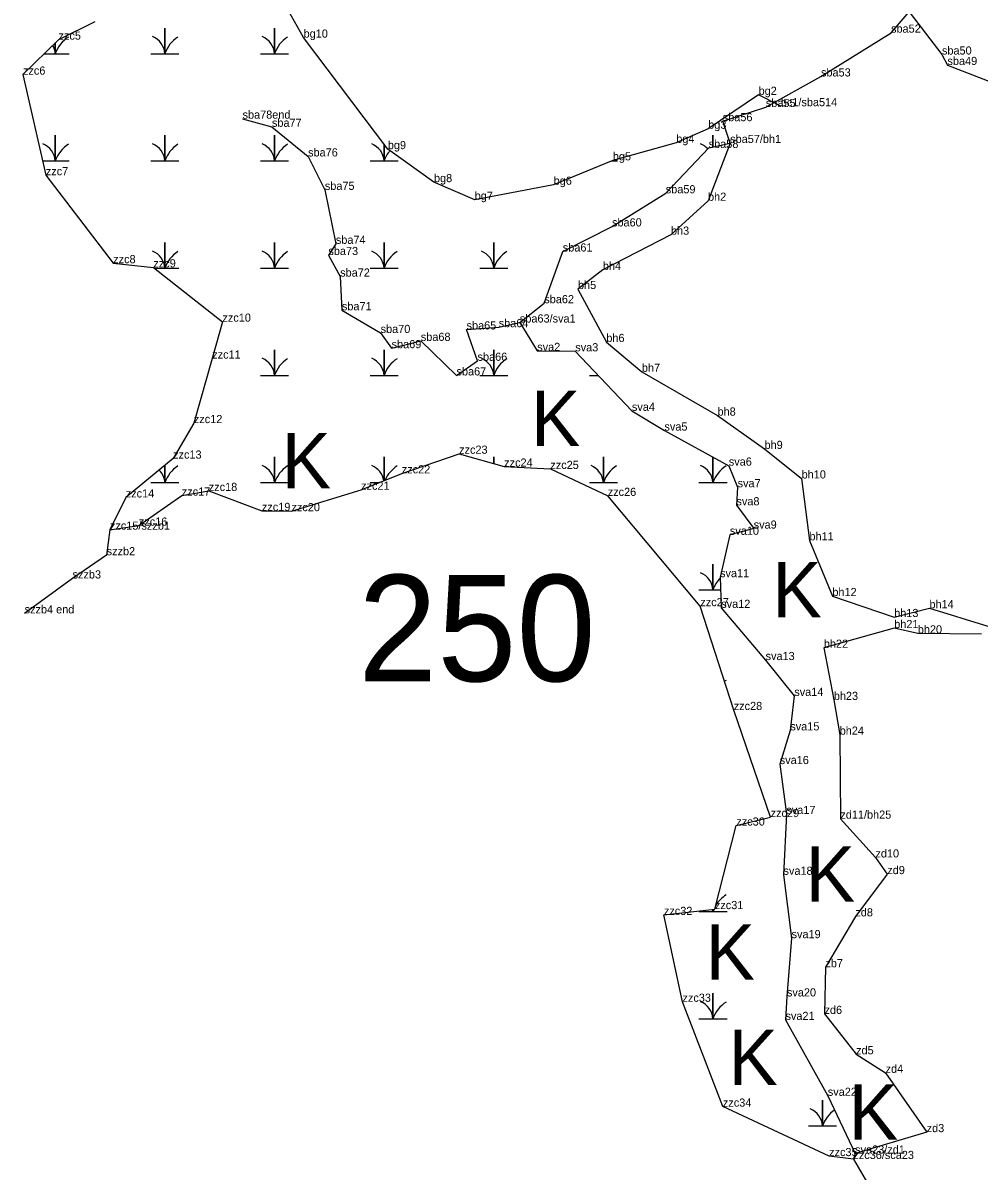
# Model space of a CAD drawing. Extents: x 2072529 to 2268796, y 436423 to 470406.
# Drawn here: x 2211555 to 2212142, y 440022 to 440726 of the extents above; entities that cross this region are included whole.
import ezdxf

# ---------------------------------------------------------------- set-up
doc = ezdxf.new("R2010")
doc.units = 0
for name, color, linetype in [('Default', 7, 'Continuous'), ('Exist Environmental Wetland Boundary', 7, 'Continuous'), ('Exist Environmental Wetland Boundary Cogo Comment', 7, 'Continuous'), ('Exist Hydro Jurisdictional Stream or Body of Water NEU Mitigable', 7, 'Continuous'), ('Exist Hydro Jurisdictional Stream or Body of Water NEU Mitigable Cogo Comment', 7, 'Continuous'), ('Exist Hydro Swamp or Marsh', 7, 'Continuous'), ('Old_Level_20', 7, 'Continuous')]:
    doc.layers.add(name, color=color, linetype=linetype)

msp = doc.modelspace()

# ---------------------------------------------------------------- linework, layer by layer
at = {"layer": 'Exist Environmental Wetland Boundary'}
for points in [[(2212020.07, 440675.03), (2212006.43, 440682), (2211975.5, 440661.2), (2211955.93, 440652.57), (2211917, 440641.78), (2211880.68, 440626.83), (2211832.24, 440617.61), (2211807.27, 440628.42), (2211778.97, 440648.69), (2211727.28, 440717.11), (2211717.96, 440733.5)], [(2211599.12, 440726.88), (2211576.92, 440715.86), (2211555.11, 440694.4), (2211569.12, 440632.64), (2211610.45, 440578.68), (2211635.11, 440576.11), (2211677.48, 440542.8), (2211671.21, 440520.15), (2211659.96, 440480.57), (2211647.22, 440458.77), (2211618.17, 440434.92), (2211608.46, 440415.15), (2211626.21, 440417.64), (2211652.55, 440436.05), (2211669.1, 440438.91), (2211701.69, 440426.65), (2211719.83, 440426.51), (2211762.55, 440439.65), (2211787.51, 440449.71), (2211822.68, 440461.76), (2211850.33, 440453.85), (2211878.65, 440452.42), (2211913.86, 440435.88)], [(2211988.98, 440652.44), (2211975.4, 440617), (2211952.66, 440596.19), (2211910.87, 440574.52), (2211895.62, 440562.82), (2211913.01, 440530.33), (2211934.81, 440512.04), (2211981.23, 440485.15), (2212010.06, 440464.72), (2212032.82, 440446.59), (2212037.61, 440408.61), (2212051.68, 440374.42), (2212089.59, 440361.54), (2212111.25, 440366.96), (2212147.05, 440355.87)], [(2212064.56, 440028.96), (2212049.69, 440030.74), (2211984.51, 440061.11), (2211959.71, 440125.46), (2211948.32, 440178.74), (2211979.6, 440182.31), (2211992.76, 440233.59), (2212013.8, 440238.8), (2211991.16, 440304.5), (2211970.67, 440368.22), (2211913.86, 440435.88)], [(2212143.11, 440351.05), (2212104.1, 440351.49), (2212089.64, 440354.75), (2212046.45, 440342.68), (2212052.57, 440310.67), (2212056.18, 440289.36), (2212056.58, 440237.81), (2212078.1, 440214), (2212085.36, 440203.8), (2212065.77, 440177.84), (2212047.38, 440146.64), (2212046.85, 440117.99), (2212066.23, 440093.22), (2212084.33, 440081.87), (2212109.54, 440045.45), (2212065.67, 440032.29)]]:
    msp.add_lwpolyline(points, dxfattribs=at)
at = {"layer": 'Exist Hydro Jurisdictional Stream or Body of Water NEU Mitigable'}
for points in [[(2211689.83, 440667.36), (2211707.85, 440662.39), (2211730.03, 440644.2), (2211740.31, 440623.69), (2211747.06, 440590.59), (2211742.49, 440583.7), (2211749.71, 440570.47), (2211750.77, 440549.79), (2211774.54, 440535.87), (2211781.27, 440526.52), (2211799.19, 440531.02), (2211821.09, 440509.82), (2211834, 440518.8), (2211827.26, 440538.02), (2211846.98, 440539.42), (2211859.97, 440542.28), (2211874.94, 440554.14), (2211886.3, 440585.87), (2211916.49, 440601.25), (2211949.48, 440621.58), (2211975.8, 440649.4), (2211988.98, 440652.44), (2211984.44, 440665.82), (2212010.84, 440674.52), (2212044.7, 440693.29), (2212087.68, 440720.16), (2212098.89, 440732.89), (2212118.92, 440706.73), (2212122.3, 440700.31), (2212150.31, 440689.4)], [(2211859.97, 440542.28), (2211870.61, 440524.83), (2211893.94, 440524.61), (2211928.71, 440488.08), (2211948.65, 440475.96), (2211988.14, 440454.44), (2211993.55, 440441.2), (2211992.83, 440430.12), (2212003.41, 440415.8), (2211988.8, 440412.02), (2211982.78, 440386.01), (2211983.49, 440367.18), (2212010.7, 440335.15), (2212028.31, 440313.12), (2212025.88, 440291.99), (2212019.4, 440271.32), (2212023.47, 440240.67), (2212021.7, 440203.38), (2212026.64, 440164.49), (2212023.8, 440128.72), (2212022.92, 440114.3), (2212048.88, 440067.75), (2212065.67, 440032.29), (2212064.56, 440028.96), (2212076.06, 440009.22)], [(2211608.46, 440415.15), (2211606.45, 440399.48), (2211585.53, 440385.21), (2211556.12, 440363.79)]]:
    msp.add_lwpolyline(points, dxfattribs=at)
at = {"layer": 'Exist Hydro Swamp or Marsh'}
for points in [[(2211633.58, 440707.24), (2211642.19, 440707.24), (2211642.19, 440723.02), (2211642.19, 440707.24), (2211650.79, 440707.24)], [(2211700.83, 440707.24), (2211709.44, 440707.24), (2211709.44, 440723.02), (2211709.44, 440707.24), (2211718.04, 440707.24)], [(2211568.15, 440707.24), (2211574.94, 440707.24), (2211574.94, 440713.91)], [(2211574.94, 440713.91), (2211574.94, 440707.24), (2211583.54, 440707.24)], [(2211567.12, 440641.44), (2211574.94, 440641.44), (2211574.94, 440657.22), (2211574.94, 440641.44), (2211583.54, 440641.44)], [(2211633.58, 440641.44), (2211642.19, 440641.44), (2211642.19, 440657.22), (2211642.19, 440641.44), (2211650.79, 440641.44)], [(2211700.83, 440641.44), (2211709.44, 440641.44), (2211709.44, 440657.22), (2211709.44, 440641.44), (2211718.04, 440641.44)], [(2211978.44, 440650.01), (2211978.44, 440657.22), (2211978.44, 440650.01)], [(2211768.08, 440641.44), (2211776.69, 440641.44), (2211776.69, 440651.72)], [(2211776.69, 440651.72), (2211776.69, 440641.44), (2211785.29, 440641.44)], [(2211916.17, 440641.44), (2211919.79, 440641.44)], [(2211635.71, 440575.64), (2211642.19, 440575.64), (2211642.19, 440591.42), (2211642.19, 440575.64), (2211650.79, 440575.64)], [(2211700.83, 440575.64), (2211709.44, 440575.64), (2211709.44, 440591.42), (2211709.44, 440575.64), (2211718.04, 440575.64)], [(2211768.08, 440575.64), (2211776.69, 440575.64), (2211776.69, 440591.42), (2211776.69, 440575.64), (2211785.29, 440575.64)], [(2211835.33, 440575.64), (2211843.94, 440575.64), (2211843.94, 440591.42), (2211843.94, 440575.64), (2211852.54, 440575.64)], [(2211700.83, 440509.84), (2211709.44, 440509.84), (2211709.44, 440525.62), (2211709.44, 440509.84), (2211718.04, 440509.84)], [(2211768.08, 440509.84), (2211776.69, 440509.84), (2211776.69, 440525.62), (2211776.69, 440509.84), (2211785.29, 440509.84)], [(2211835.33, 440509.84), (2211843.94, 440509.84), (2211843.94, 440525.62), (2211843.94, 440509.84), (2211852.54, 440509.84)], [(2211902.58, 440509.84), (2211908, 440509.84)], [(2211700.83, 440444.04), (2211709.44, 440444.04), (2211709.44, 440459.82), (2211709.44, 440444.04), (2211718.04, 440444.04)], [(2211776.69, 440445.34), (2211776.69, 440459.82), (2211776.69, 440445.34)], [(2211843.94, 440455.68), (2211843.94, 440459.82), (2211843.94, 440455.68)], [(2211902.58, 440444.04), (2211911.19, 440444.04), (2211911.19, 440459.82), (2211911.19, 440444.04), (2211919.79, 440444.04)], [(2211969.83, 440444.04), (2211978.44, 440444.04), (2211978.44, 440459.73)], [(2211978.44, 440459.73), (2211978.44, 440444.04), (2211987.04, 440444.04)], [(2211633.58, 440444.04), (2211642.19, 440444.04), (2211642.19, 440454.63)], [(2211642.19, 440454.63), (2211642.19, 440444.04), (2211650.79, 440444.04)], [(2211768.08, 440444.04), (2211773.44, 440444.04)], [(2211969.83, 440378.24), (2211978.44, 440378.24), (2211978.44, 440394.02), (2211978.44, 440378.24), (2211983.07, 440378.24)], [(2211969.83, 440180.84), (2211978.44, 440180.84), (2211978.44, 440182.18)], [(2211978.44, 440182.18), (2211978.44, 440180.84), (2211987.04, 440180.84)], [(2211969.83, 440115.04), (2211978.44, 440115.04), (2211978.44, 440130.82), (2211978.44, 440115.04), (2211987.04, 440115.04)], [(2212037.08, 440049.24), (2212045.69, 440049.24), (2212045.69, 440065.02), (2212045.69, 440049.24), (2212054.29, 440049.24)]]:
    msp.add_lwpolyline(points, dxfattribs=at)
for centre, radius, start, end in [((2211593.18, 440701.18), 19.22, 122.12745, 161.62219), ((2211629.92, 440706.35), 12.3, 4.14034, 67.53497), ((2211660.43, 440701.18), 19.22, 122.12745, 161.62219), ((2211697.17, 440706.35), 12.3, 4.14034, 67.53497), ((2211727.68, 440701.18), 19.22, 122.12745, 161.62219), ((2211562.67, 440706.35), 12.3, 4.14034, 29.39022), ((2211562.67, 440640.55), 12.3, 4.14034, 67.53497), ((2211593.18, 440635.38), 19.22, 122.12745, 161.62219), ((2211629.92, 440640.55), 12.3, 4.14034, 67.53497), ((2211660.43, 440635.38), 19.22, 122.12745, 161.62219), ((2211697.17, 440640.55), 12.3, 4.14034, 67.53497), ((2211727.68, 440635.38), 19.22, 122.12745, 161.62219), ((2211764.42, 440640.55), 12.3, 4.14034, 67.53497), ((2211794.93, 440635.38), 19.22, 139.80689, 161.62219), ((2211966.17, 440640.55), 12.3, 42.34122, 67.53497), ((2211629.92, 440574.75), 12.3, 4.14034, 67.53497), ((2211660.43, 440569.58), 19.22, 122.12745, 161.62219), ((2211697.17, 440574.75), 12.3, 4.14034, 67.53497), ((2211727.68, 440569.58), 19.22, 122.12745, 161.62219), ((2211764.42, 440574.75), 12.3, 4.14034, 67.53497), ((2211794.93, 440569.58), 19.22, 122.12745, 161.62219), ((2211831.67, 440574.75), 12.3, 4.14034, 67.53497), ((2211862.18, 440569.58), 19.22, 122.12745, 161.62219), ((2211697.17, 440508.95), 12.3, 4.14034, 67.53497), ((2211727.68, 440503.78), 19.22, 122.12745, 161.62219), ((2211764.42, 440508.95), 12.3, 4.14034, 67.53497), ((2211794.93, 440503.78), 19.22, 122.12745, 161.62219), ((2211831.67, 440508.95), 12.3, 4.14034, 67.53497), ((2211862.18, 440503.78), 19.22, 122.12745, 161.62219), ((2211629.92, 440443.15), 12.3, 4.14034, 44.48978), ((2211660.43, 440437.98), 19.22, 122.12745, 161.62219), ((2211697.17, 440443.15), 12.3, 4.14034, 67.53497), ((2211727.68, 440437.98), 19.22, 122.12745, 161.62219), ((2211764.42, 440443.15), 12.3, 9.98945, 67.53497), ((2211794.93, 440437.98), 19.22, 122.12745, 156.69385), ((2211862.18, 440437.98), 19.22, 122.12745, 124.5773), ((2211898.92, 440443.15), 12.3, 4.14034, 67.53497), ((2211929.43, 440437.98), 19.22, 122.12745, 161.62219), ((2211966.17, 440443.15), 12.3, 4.14034, 67.53497), ((2211996.68, 440437.98), 19.22, 122.12745, 161.62219), ((2211966.17, 440377.35), 12.3, 4.14034, 67.53497), ((2211996.68, 440372.18), 19.22, 136.23499, 161.62219), ((2211996.68, 440306.38), 19.22, 122.12745, 125.46334), ((2211996.68, 440174.78), 19.22, 122.12745, 148.92072), ((2211966.17, 440179.95), 12.3, 4.14034, 10.36494), ((2211996.68, 440174.78), 19.22, 157.14906, 161.62219), ((2211966.17, 440114.15), 12.3, 4.14034, 67.53497), ((2211996.68, 440108.98), 19.22, 122.12745, 161.62219), ((2212033.42, 440048.35), 12.3, 4.14034, 67.53497), ((2212063.93, 440043.18), 19.22, 124.57887, 161.62219)]:
    msp.add_arc(centre, radius, start, end, dxfattribs=at)
at = {"layer": 'Old_Level_20'}
for p, q in [((2211576.92, 440715.86), (2211576.92, 440715.86)), ((2211727.28, 440717.11), (2211727.28, 440717.11)), ((2212087.68, 440720.16), (2212087.68, 440720.16)), ((2212118.92, 440706.73), (2212118.92, 440706.73)), ((2212122.3, 440700.31), (2212122.3, 440700.31)), ((2211555.11, 440694.4), (2211555.11, 440694.4)), ((2212044.7, 440693.29), (2212044.7, 440693.29)), ((2212006.43, 440682), (2212006.43, 440682)), ((2212010.84, 440674.52), (2212010.84, 440674.52)), ((2212020.07, 440675.03), (2212020.07, 440675.03)), ((2211689.83, 440667.36), (2211689.83, 440667.36)), ((2211707.85, 440662.39), (2211707.85, 440662.39)), ((2211975.5, 440661.2), (2211975.5, 440661.2)), ((2211984.44, 440665.82), (2211984.44, 440665.82)), ((2211955.93, 440652.57), (2211955.93, 440652.57)), ((2211988.98, 440652.44), (2211988.98, 440652.44)), ((2211988.98, 440652.44), (2211988.98, 440652.44)), ((2211778.97, 440648.69), (2211778.97, 440648.69)), ((2211975.8, 440649.4), (2211975.8, 440649.4)), ((2211730.03, 440644.2), (2211730.03, 440644.2)), ((2211917, 440641.78), (2211917, 440641.78)), ((2211569.12, 440632.64), (2211569.12, 440632.64)), ((2211807.27, 440628.42), (2211807.27, 440628.42)), ((2211880.68, 440626.83), (2211880.68, 440626.83)), ((2211740.31, 440623.69), (2211740.31, 440623.69)), ((2211832.24, 440617.61), (2211832.24, 440617.61)), ((2211949.48, 440621.58), (2211949.48, 440621.58)), ((2211975.4, 440617), (2211975.4, 440617)), ((2211916.49, 440601.25), (2211916.49, 440601.25)), ((2211952.66, 440596.19), (2211952.66, 440596.19)), ((2211747.06, 440590.59), (2211747.06, 440590.59)), ((2211742.49, 440583.7), (2211742.49, 440583.7)), ((2211886.3, 440585.87), (2211886.3, 440585.87)), ((2211610.45, 440578.68), (2211610.45, 440578.68)), ((2211635.11, 440576.11), (2211635.11, 440576.11)), ((2211749.71, 440570.47), (2211749.71, 440570.47)), ((2211910.87, 440574.52), (2211910.87, 440574.52)), ((2211895.62, 440562.82), (2211895.62, 440562.82)), ((2211874.94, 440554.14), (2211874.94, 440554.14)), ((2211750.77, 440549.79), (2211750.77, 440549.79)), ((2211677.48, 440542.8), (2211677.48, 440542.8)), ((2211859.97, 440542.28), (2211859.97, 440542.28)), ((2211774.54, 440535.87), (2211774.54, 440535.87)), ((2211827.26, 440538.02), (2211827.26, 440538.02)), ((2211846.98, 440539.42), (2211846.98, 440539.42)), ((2211781.27, 440526.52), (2211781.27, 440526.52)), ((2211799.19, 440531.02), (2211799.19, 440531.02)), ((2211913.01, 440530.33), (2211913.01, 440530.33)), ((2211671.21, 440520.15), (2211671.21, 440520.15)), ((2211834, 440518.8), (2211834, 440518.8)), ((2211870.61, 440524.83), (2211870.61, 440524.83)), ((2211893.94, 440524.61), (2211893.94, 440524.61)), ((2211934.81, 440512.04), (2211934.81, 440512.04)), ((2211821.09, 440509.82), (2211821.09, 440509.82)), ((2211928.71, 440488.08), (2211928.71, 440488.08)), ((2211981.23, 440485.15), (2211981.23, 440485.15)), ((2211659.96, 440480.57), (2211659.96, 440480.57)), ((2211948.65, 440475.96), (2211948.65, 440475.96)), ((2212010.06, 440464.72), (2212010.06, 440464.72)), ((2211647.22, 440458.77), (2211647.22, 440458.77)), ((2211822.68, 440461.76), (2211822.68, 440461.76)), ((2211787.51, 440449.71), (2211787.51, 440449.71)), ((2211850.33, 440453.85), (2211850.33, 440453.85)), ((2211878.65, 440452.42), (2211878.65, 440452.42)), ((2211988.14, 440454.44), (2211988.14, 440454.44)), ((2211993.55, 440441.2), (2211993.55, 440441.2)), ((2212032.82, 440446.59), (2212032.82, 440446.59)), ((2211618.17, 440434.92), (2211618.17, 440434.92)), ((2211652.55, 440436.05), (2211652.55, 440436.05)), ((2211669.1, 440438.91), (2211669.1, 440438.91)), ((2211762.55, 440439.65), (2211762.55, 440439.65)), ((2211913.86, 440435.88), (2211913.86, 440435.88)), ((2211992.83, 440430.12), (2211992.83, 440430.12)), ((2211701.69, 440426.65), (2211701.69, 440426.65)), ((2211719.83, 440426.51), (2211719.83, 440426.51)), ((2211608.46, 440415.15), (2211608.46, 440415.15)), ((2211608.46, 440415.15), (2211608.46, 440415.15)), ((2211626.21, 440417.64), (2211626.21, 440417.64)), ((2212003.41, 440415.8), (2212003.41, 440415.8)), ((2211988.8, 440412.02), (2211988.8, 440412.02)), ((2212037.61, 440408.61), (2212037.61, 440408.61)), ((2211606.45, 440399.48), (2211606.45, 440399.48)), ((2211606.45, 440399.48), (2211606.45, 440399.48)), ((2211585.53, 440385.21), (2211585.53, 440385.21)), ((2211585.53, 440385.21), (2211585.53, 440385.21)), ((2211982.78, 440386.01), (2211982.78, 440386.01)), ((2212051.68, 440374.42), (2212051.68, 440374.42)), ((2211556.12, 440363.79), (2211556.12, 440363.79)), ((2211556.12, 440363.79), (2211556.12, 440363.79)), ((2211970.67, 440368.22), (2211970.67, 440368.22)), ((2211983.49, 440367.18), (2211983.49, 440367.18)), ((2212111.25, 440366.96), (2212111.25, 440366.96)), ((2212089.59, 440361.54), (2212089.59, 440361.54)), ((2212089.64, 440354.75), (2212089.64, 440354.75)), ((2212104.1, 440351.49), (2212104.1, 440351.49)), ((2212046.45, 440342.68), (2212046.45, 440342.68)), ((2212010.7, 440335.15), (2212010.7, 440335.15)), ((2212028.31, 440313.12), (2212028.31, 440313.12)), ((2212052.57, 440310.67), (2212052.57, 440310.67)), ((2211991.16, 440304.5), (2211991.16, 440304.5)), ((2212025.88, 440291.99), (2212025.88, 440291.99)), ((2212056.18, 440289.36), (2212056.18, 440289.36)), ((2212019.4, 440271.32), (2212019.4, 440271.32)), ((2212013.8, 440238.8), (2212013.8, 440238.8)), ((2212023.47, 440240.67), (2212023.47, 440240.67)), ((2212056.58, 440237.81), (2212056.58, 440237.81)), ((2211992.76, 440233.59), (2211992.76, 440233.59)), ((2212078.1, 440214), (2212078.1, 440214)), ((2212021.7, 440203.38), (2212021.7, 440203.38)), ((2212085.36, 440203.8), (2212085.36, 440203.8)), ((2211979.6, 440182.31), (2211979.6, 440182.31)), ((2211948.32, 440178.74), (2211948.32, 440178.74)), ((2212065.77, 440177.84), (2212065.77, 440177.84)), ((2212026.64, 440164.49), (2212026.64, 440164.49)), ((2212047.38, 440146.64), (2212047.38, 440146.64)), ((2211959.71, 440125.46), (2211959.71, 440125.46)), ((2212023.8, 440128.72), (2212023.8, 440128.72)), ((2212046.85, 440117.99), (2212046.85, 440117.99)), ((2212022.92, 440114.3), (2212022.92, 440114.3)), ((2212066.23, 440093.22), (2212066.23, 440093.22)), ((2212084.33, 440081.87), (2212084.33, 440081.87)), ((2212048.88, 440067.75), (2212048.88, 440067.75)), ((2211984.51, 440061.11), (2211984.51, 440061.11)), ((2212109.54, 440045.45), (2212109.54, 440045.45)), ((2212049.69, 440030.74), (2212049.69, 440030.74)), ((2212064.56, 440028.96), (2212064.56, 440028.96)), ((2212064.56, 440028.96), (2212064.56, 440028.96)), ((2212065.67, 440032.29), (2212065.67, 440032.29)), ((2212065.67, 440032.29), (2212065.67, 440032.29))]:
    msp.add_line(p, q, dxfattribs=at)

# ---------------------------------------------------------------- texts
at = {"layer": 'Default'}
msp.add_text('250', height=65.34, dxfattribs=at).set_placement((2211760.71, 440322.11))
at = {"layer": 'Exist Environmental Wetland Boundary Cogo Comment'}
for s, p in [('zzc5', (2211576.92, 440715.86)), ('bg10', (2211727.28, 440717.11)), ('zzc6', (2211555.11, 440694.4)), ('bg2', (2212006.43, 440682)), ('bc1/sba514', (2212020.07, 440675.03)), ('bg3', (2211975.5, 440661.2)), ('bg9', (2211778.97, 440648.69)), ('bg4', (2211955.93, 440652.57)), ('sba57/bh1', (2211988.98, 440652.44)), ('bg5', (2211917, 440641.78)), ('zzc7', (2211569.12, 440632.64)), ('bg8', (2211807.27, 440628.42)), ('bg6', (2211880.68, 440626.83)), ('bg7', (2211832.24, 440617.61)), ('bh2', (2211975.4, 440617)), ('bh3', (2211952.66, 440596.19)), ('zzc8', (2211610.45, 440578.68)), ('zzc9', (2211635.11, 440576.11)), ('bh4', (2211910.87, 440574.52)), ('bh5', (2211895.62, 440562.82)), ('zzc10', (2211677.48, 440542.8)), ('bh6', (2211913.01, 440530.33)), ('zzc11', (2211671.21, 440520.15)), ('bh7', (2211934.81, 440512.04)), ('bh8', (2211981.23, 440485.15)), ('zzc12', (2211659.96, 440480.57)), ('bh9', (2212010.06, 440464.72)), ('zzc13', (2211647.22, 440458.77)), ('zzc23', (2211822.68, 440461.76)), ('zzc24', (2211850.33, 440453.85)), ('zzc25', (2211878.65, 440452.42)), ('zzc22', (2211787.51, 440449.71)), ('bh10', (2212032.82, 440446.59)), ('zzc17', (2211652.55, 440436.05)), ('zzc18', (2211669.1, 440438.91)), ('zzc21', (2211762.55, 440439.65)), ('zzc14', (2211618.17, 440434.92)), ('zzc26', (2211913.86, 440435.88)), ('zzc19', (2211701.69, 440426.65)), ('zzc20', (2211719.83, 440426.51)), ('zzc16', (2211626.21, 440417.64)), ('bh11', (2212037.61, 440408.61)), ('bh12', (2212051.68, 440374.42)), ('zzc27', (2211970.67, 440368.22)), ('bh14', (2212111.25, 440366.96)), ('bh13', (2212089.59, 440361.54)), ('bh21', (2212089.64, 440354.75)), ('bh20', (2212104.1, 440351.49)), ('bh22', (2212046.45, 440342.68)), ('bh23', (2212052.57, 440310.67)), ('zzc28', (2211991.16, 440304.5)), ('bh24', (2212056.18, 440289.36)), ('zzc30', (2211992.76, 440233.59)), ('zd11/bh25', (2212056.58, 440237.81)), ('zd10', (2212078.1, 440214)), ('zd9', (2212085.36, 440203.8)), ('zzc32', (2211948.32, 440178.74)), ('zzc31', (2211979.6, 440182.31)), ('zd8', (2212065.77, 440177.84)), ('zb7', (2212047.38, 440146.64)), ('zzc33', (2211959.71, 440125.46)), ('zd6', (2212046.85, 440117.99)), ('zd5', (2212066.23, 440093.22)), ('zd4', (2212084.33, 440081.87)), ('zzc34', (2211984.51, 440061.11)), ('zd3', (2212109.54, 440045.45)), ('zzc35', (2212049.69, 440030.74)), ('sva23/zd1', (2212065.67, 440032.29))]:
    msp.add_text(s, height=5, dxfattribs=at).set_placement(p)
at = {"layer": 'Exist Hydro Jurisdictional Stream or Body of Water NEU Mitigable Cogo Comment'}
for s, p in [('sba52', (2212087.68, 440720.16)), ('sba50', (2212118.92, 440706.73)), ('sba49', (2212122.3, 440700.31)), ('sba53', (2212044.7, 440693.29)), ('sba55', (2212010.84, 440674.52)), ('sba78end', (2211689.83, 440667.36)), ('sba77', (2211707.85, 440662.39)), ('sba56', (2211984.44, 440665.82)), ('sba58', (2211975.8, 440649.4)), ('sba76', (2211730.03, 440644.2)), ('sba75', (2211740.31, 440623.69)), ('sba59', (2211949.48, 440621.58)), ('sba60', (2211916.49, 440601.25)), ('sba74', (2211747.06, 440590.59)), ('sba61', (2211886.3, 440585.87)), ('sba73', (2211742.49, 440583.7)), ('sba72', (2211749.71, 440570.47)), ('sba71', (2211750.77, 440549.79)), ('sba62', (2211874.94, 440554.14)), ('sba63/sva1', (2211859.97, 440542.28)), ('sba70', (2211774.54, 440535.87)), ('sba65', (2211827.26, 440538.02)), ('sba64', (2211846.98, 440539.42)), ('sba68', (2211799.19, 440531.02)), ('sba69', (2211781.27, 440526.52)), ('sva2', (2211870.61, 440524.83)), ('sva3', (2211893.94, 440524.61)), ('sba66', (2211834, 440518.8)), ('sba67', (2211821.09, 440509.82)), ('sva4', (2211928.71, 440488.08)), ('sva5', (2211948.65, 440475.96)), ('sva6', (2211988.14, 440454.44)), ('sva7', (2211993.55, 440441.2)), ('sva8', (2211992.83, 440430.12)), ('zzc15/szzb', (2211608.46, 440415.15)), ('zzc15/szzb1', (2211608.46, 440415.15)), ('sva9', (2212003.41, 440415.8)), ('sva10', (2211988.8, 440412.02)), ('szzb2', (2211606.45, 440399.48)), ('szzb3', (2211585.53, 440385.21)), ('sva11', (2211982.78, 440386.01)), ('sva12', (2211983.49, 440367.18)), ('szzb4 end', (2211556.12, 440363.79)), ('sva13', (2212010.7, 440335.15)), ('sva14', (2212028.31, 440313.12)), ('sva15', (2212025.88, 440291.99)), ('sva16', (2212019.4, 440271.32)), ('zzc29', (2212013.8, 440238.8)), ('sva17', (2212023.47, 440240.67)), ('sva18', (2212021.7, 440203.38)), ('sva19', (2212026.64, 440164.49)), ('sva20', (2212023.8, 440128.72)), ('sva21', (2212022.92, 440114.3)), ('sva22', (2212048.88, 440067.75)), ('zzc36/sca23', (2212064.56, 440028.96))]:
    msp.add_text(s, height=5, dxfattribs=at).set_placement(p)
at = {"layer": 'Exist Hydro Swamp or Marsh'}
for p in [(2211866.71, 440466.43), (2211713.73, 440440.58), (2212014.84, 440361.4), (2212035.31, 440186.87), (2211973.91, 440138.93), (2211987.91, 440074.29), (2212061.71, 440040.9)]:
    msp.add_text('K', height=34, dxfattribs=at).set_placement(p)

doc.saveas('drawing.dxf')
